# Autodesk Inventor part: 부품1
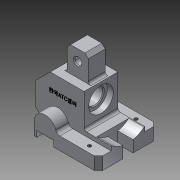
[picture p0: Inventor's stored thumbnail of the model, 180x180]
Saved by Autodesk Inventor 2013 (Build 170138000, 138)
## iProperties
Created: 2016-11
Part Number: 부품1
Material: 알루미늄 6061
Document SubType Name: Modeling
Designer: default
Density: 2.71 g/cm^3
Mass: 462.555 g
Surface Area: 317.832 cm^2
Volume: 170.685 cm^3
Author: default
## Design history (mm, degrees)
sketch "스케치1"
  geometry: L1 (45, -35)-(-45, -35); L2 (-45, -35)-(-45, 35); L3 (-45, 35)-(45, 35); L4 (45, 35)-(45, -35); L5 (45, -35)-(-45, 35); L6 (-45, -35)-(45, 35); 1 further point
  constraints: 12 end point, 2 midpoint, 2 parallel, 1 horizontal, 1 perpendicular
  dimensions: "d0" = 90 distance of L2.end L3.end; "d2" = 70 distance of L1.end L2.end
extrude "돌출1" new body sketch "스케치1" distance "d6" = 90; taper "d7" = 0 deg
sketch "스케치2"
  geometry: L1 (90, 0)-(0, 0) reference; L2 (90, 0)-(90, 90) reference; L3 (0, 90)-(90, 90) reference; L4 (0, 0)-(0, 90) reference; L5 (90, 20)-(58, 20); L6 (58, 20)-(58, 60); L7 (58, 60)-(53, 60); L8 (53, 60)-(53, 90); 1 further point
  constraints: 8 end point, 3 perpendicular, 2 point on line, 1 parallel
  dimensions: "d8" = 20 distance between parallel lines of L1 L5; "d9" = 58 distance between parallel lines of L4 L6; "d10" = 5 distance between parallel lines of L8 L6; "d11" = 60 distance between parallel lines of L1 L7
extrude "돌출2" cut sketch "스케치2" distance "d12" = 90; taper "d13" = 0 deg
sketch "스케치3"
  geometry: L1 (60, 70)-(60, 0) reference; C1 r 14.5 at (18, 35); 2 further points
  constraints: 1 centre point, 1 horizontal alignment, 1 midpoint
  dimensions: "d14" = 29 diameter of C1; "d16" = 42 distance from line of L1 C1.centre
extrude "돌출3" cut sketch "스케치3" distance "d17" = 7; taper "d18" = 0 deg
sketch "스케치4"
  geometry: C1 r 14.5 at (0, 0) reference; C2 r 10 at (0, 0); 1 further point
  constraints: 1 centre point, 1 coincident
  dimensions: "d19" = 20 diameter of C2
extrude "돌출4" cut sketch "스케치4" stored distance "d21" = 7; taper "d22" = 0 deg
sketch "스케치5"
  geometry: L1 (0, 70)-(30, 70) reference; L2 (0, 0)-(0, 70) reference; L3 (30, 0)-(0, 0) reference; L4 (30, 0)-(30, 70) reference; L5 (0, 35)-(30, 35); L6 (0, 25)-(30, 25); L7 (0, 45)-(30, 45); 1 further point
  constraints: 6 end point, 4 point on line, 2 midpoint, 2 perpendicular
  dimensions: "d23" = 20 distance between parallel lines of L7 L6; "d25" = 10 distance between parallel lines of L6 L5
extrude "돌출5" cut sketch "스케치5" stored distance "d26" = 7; taper "d27" = 0 deg
sketch "스케치6"
  geometry: L1 (0, 70)-(40, 70) reference; L2 (0, 0)-(0, 70) reference; L3 (40, 0)-(0, 0) reference; L4 (40, 0)-(40, 70) reference; L5 (0, 15)-(40, 15); L6 (0, 55)-(40, 55); C1 r 14.5 at (18, 35) reference; 1 further point
  constraints: 4 end point, 4 point on line, 2 perpendicular, 1 parallel
  dimensions: "d28" = 40 distance between parallel lines of L5 L6; "d29" = 20 distance from line of C1.centre L5
extrude "돌출6" cut sketch "스케치6" stored distance "d30" = 7; taper "d31" = 0 deg
sketch "스케치7"
  geometry: L1 (90, 20)-(0, 20) reference; L2 (0, 0)-(0, 20) reference; L3 (90, 0)-(0, 0) reference; L4 (90, 0)-(90, 20) reference; L5 (14, 15)-(14, 0); L6 (14, 0)-(17, 0); L7 (17, 0)-(17, 7); L8 (37, 7)-(37, 0); L9 (17, 7)-(37, 7); L10 (27, 15)-(90, 15); L11 (15, 20)-(0, 20); L12 (0, 0)-(0, 20); L13 (0, 0)-(14, 0); L14 (39, 20)-(90, 20); L15 (90, 15)-(90, 20); A1 r 13 centre (27, 15) between (40, 15) and (14, 15); 1 further point
  constraints: 23 end point, 8 point on line, 5 perpendicular, 4 point on circle, 3 collinear, 3 parallel, 1 centre point, 1 tangent
  dimensions: "d32" = 26 diameter of A1; "d34" = 15 distance from line of L3 L10.start; "d35" = 63 distance from line of L4 L10.start; "d36" = 3 distance of L5.end L6.end; "d37" = 20 distance of L8.start L7.end; "d38" = 7 distance between parallel lines of L3 L9; "d39" = 7 distance of L8.start L8.end
extrude "돌출7" cut sketch "스케치7" distance "d41" = 15; taper "d42" = 0 deg
sketch "스케치8"
  geometry: L1 (-20, 0)-(-20, 7) reference; L2 (-20, 7)-(0, 7) reference; L3 (0, 7)-(0, 0) reference; L4 (53, 0)-(0, 0) reference; L5 (53, 0)-(53, 15) reference; L6 (53, 15)-(3, 15) reference; L7 (-23, 15)-(-23, 0) reference; L8 (-20, 0)-(-23, 0) reference; A1 r 13 centre (-10, 15) between (-22, 20) and (-23, 15) reference; A2 r 13 centre (-10, 15) between (3, 15) and (-23, 15); 1 further point
  constraints: 3 point on circle, 2 point on line, 1 centre point, 1 coincident
extrude "돌출8" join sketch "스케치8" distance "d43" = 15; taper "d44" = 0 deg
sketch "스케치9"
  geometry: L1 (-15, 0)-(-15, 15) reference; L2 (-15, 15)-(-20, 15) reference; L3 (-20, 15)-(-20, 55) reference; L4 (-20, 55)-(-15, 55) reference; L5 (-15, 55)-(-15, 70) reference; L6 (-15, 70)-(0, 70) reference; L7 (0, 70)-(0, 0) reference; L8 (0, 0)-(-15, 0) reference; L9 (-15, 0)-(-15, 15) reference; L10 (-15, 15)-(-20, 15) reference; L11 (-20, 15)-(-20, 55) reference; L12 (-20, 55)-(-15, 55) reference; L13 (-15, 55)-(-15, 70) reference; L14 (-15, 70)-(0, 70) reference; L15 (0, 70)-(0, 0) reference; L16 (0, 0)-(-15, 0) reference; L17 (-15, 0)-(-15, 15) reference; L18 (-15, 15)-(-20, 15) reference; L19 (-20, 15)-(-20, 55) reference; L20 (-20, 55)-(-15, 55) reference; L21 (-15, 55)-(-15, 70) reference; L22 (-15, 70)-(0, 70) reference; L23 (0, 70)-(0, 0) reference; L24 (0, 0)-(-15, 0) reference; C1 r 14.5 at (-42, 35) reference; C2 r 29 at (-42, 35); 1 further point
  constraints: 1 centre point, 1 coincident
  dimensions: "d45" = 58 diameter of C2
extrude "돌출9" cut sketch "스케치9" distance "d47" = 18; taper "d48" = 0 deg
sketch "스케치10"
  geometry: L1 (0, 70)-(0, 0) reference; L2 (-13.627, 29)-(0, 29); L3 (0, 41)-(-13.627, 41); A1 r 29 centre (-42, 35) between (-20, 16.106) and (-20, 53.894) reference; 1 further point
  constraints: 4 end point, 2 point on circle, 2 point on line, 1 parallel, 1 perpendicular
  dimensions: "d49" = 12 distance between parallel lines of L2 L3; "d50" = 6 distance from line of point (0, 35) L2
extrude "돌출10" cut sketch "스케치10" distance "d51" = 18; taper "d52" = 0 deg
chamfer "모따기1" distance "d53" = 5; stored, may be unused: second distance "d54" = 2, angle "d55" = 45 deg
sketch "스케치11"
  geometry: L1 (50, 0)-(50, -10) reference; L2 (32, 1.106)-(32, 38.894) reference; L3 (-58, 20)-(68, 20) reference; 2 further points
  dimensions: "d61" = 27.5 distance from line of L3 point (32, -7.5); "d62" = 18 distance from line of L1 point (32, -7.5)
hole "구멍1" sketch "스케치11" at (32, -7.5) diameter "d63" = 4; stored, may be unused: countersink angle "d67" = 90 deg, drill point angle "d69" = 118 deg; dims "d64" = 6, "d65" = 4, "d66" = 2, "d68" = 8
sketch "스케치12"
  geometry: L1 (37, 0)-(17, 0) reference; L2 (37, 7)-(37, 0) reference; L3 (17, 7)-(37, 7) reference; L4 (17, 0)-(17, 7) reference; 1 further point
extrude "돌출11" cut sketch "스케치12" stored distance "d70" = 18; taper "d71" = 0 deg
sketch "스케치13"
  geometry: L1 (0, 40)-(0, 0) reference; L2 (-58, 40)-(0, 40) reference; L3 (-58, -20)-(-58, 40) reference; L4 (-44, -20)-(-58, -20) reference; L5 (-44, -5)-(-44, -20) reference; L6 (-58, 22)-(0, 22); L7 (-44, -8)-(-58, -8); 1 further point
  constraints: 4 end point, 4 point on line, 1 parallel, 1 perpendicular
  dimensions: "d72" = 18 distance between parallel lines of L2 L6; "d73" = 30 distance between parallel lines of L6 L7
extrude "돌출12" cut sketch "스케치13" stored distance "d74" = 18; taper "d75" = 0 deg
sketch "스케치14"
  geometry: L1 (-53, 0)-(-53, 30) reference; L2 (0, 0)-(-53, 0) reference; L3 (0, 30)-(0, 0) reference; L4 (-53, 30)-(0, 30) reference; L5 (-25, 30)-(-25, 0); 1 further point
  constraints: 2 end point, 2 point on line, 1 perpendicular
  dimensions: "d76" = 25 distance between parallel lines of L3 L5
extrude "돌출13" cut sketch "스케치14" stored distance "d77" = 18; taper "d78" = 0 deg
sketch "스케치15"
  geometry: L1 (-58, 40)-(0, 40) reference; L2 (-58, -8)-(-58, 40) reference; L3 (-40, 40)-(-58, 22); 1 further point
  constraints: 2 end point, 2 point on line
  dimensions: "d79" = 45 deg angle of L1 L3; "d80" = 18 distance from line of L2 L3.start
extrude "돌출14" cut sketch "스케치15" stored distance "d81" = 18; taper "d82" = 0 deg
chamfer "모따기2" distance "d83" = 4; stored, may be unused: second distance "d84" = 2, angle "d85" = 45 deg
sketch "스케치16"
  geometry: L1 (-25, 30)-(-25, 0) reference; L2 (-25, 30)-(0, 30) reference; C1 r 4 at (-12.5, 17); 1 further point
  constraints: 1 centre point
  dimensions: "d86" = 8 diameter of C1; "d88" = 12.5 distance from line of C1.centre L1; "d89" = 13 distance from line of L2 C1.centre
extrude "돌출15" cut sketch "스케치16" stored distance "d90" = 18; taper "d91" = 0 deg
chamfer "모따기3" distance "d92" = 4; stored, may be unused: second distance "d93" = 2, angle "d94" = 45 deg
chamfer "모따기4" distance "d95" = 1; stored, may be unused: second distance "d96" = 2, angle "d97" = 45 deg
fillet "모깎기1" dims "d98" = 5
fillet "모깎기2" dims "d99" = 3
sketch "스케치17"
  geometry: L1 (-32, 45)-(-32, 8) reference; L2 (-72, 45)-(-32, 45) reference; 2 further points
  constraints: 1 other
  dimensions: "d100" = 18 distance from line of point (-57, 27) L2; "d101" = 25 distance from line of L1 point (-57, 27)
feature "엠보싱1" sketch "스케치17" dims "d0" = 90, "d2" = 70, "d102" = 0.5, "d103" = 0
feature "스레드1" dims "d104" = 10, "d105" = 0
feature "스레드2" dims "d106" = 10, "d107" = 0
node "솔리드1"
mirror "대칭1"
mirror "대칭2"
node "절단 모서리 투영1"
node "절단 모서리 투영2"
node "절단 모서리 투영3"
